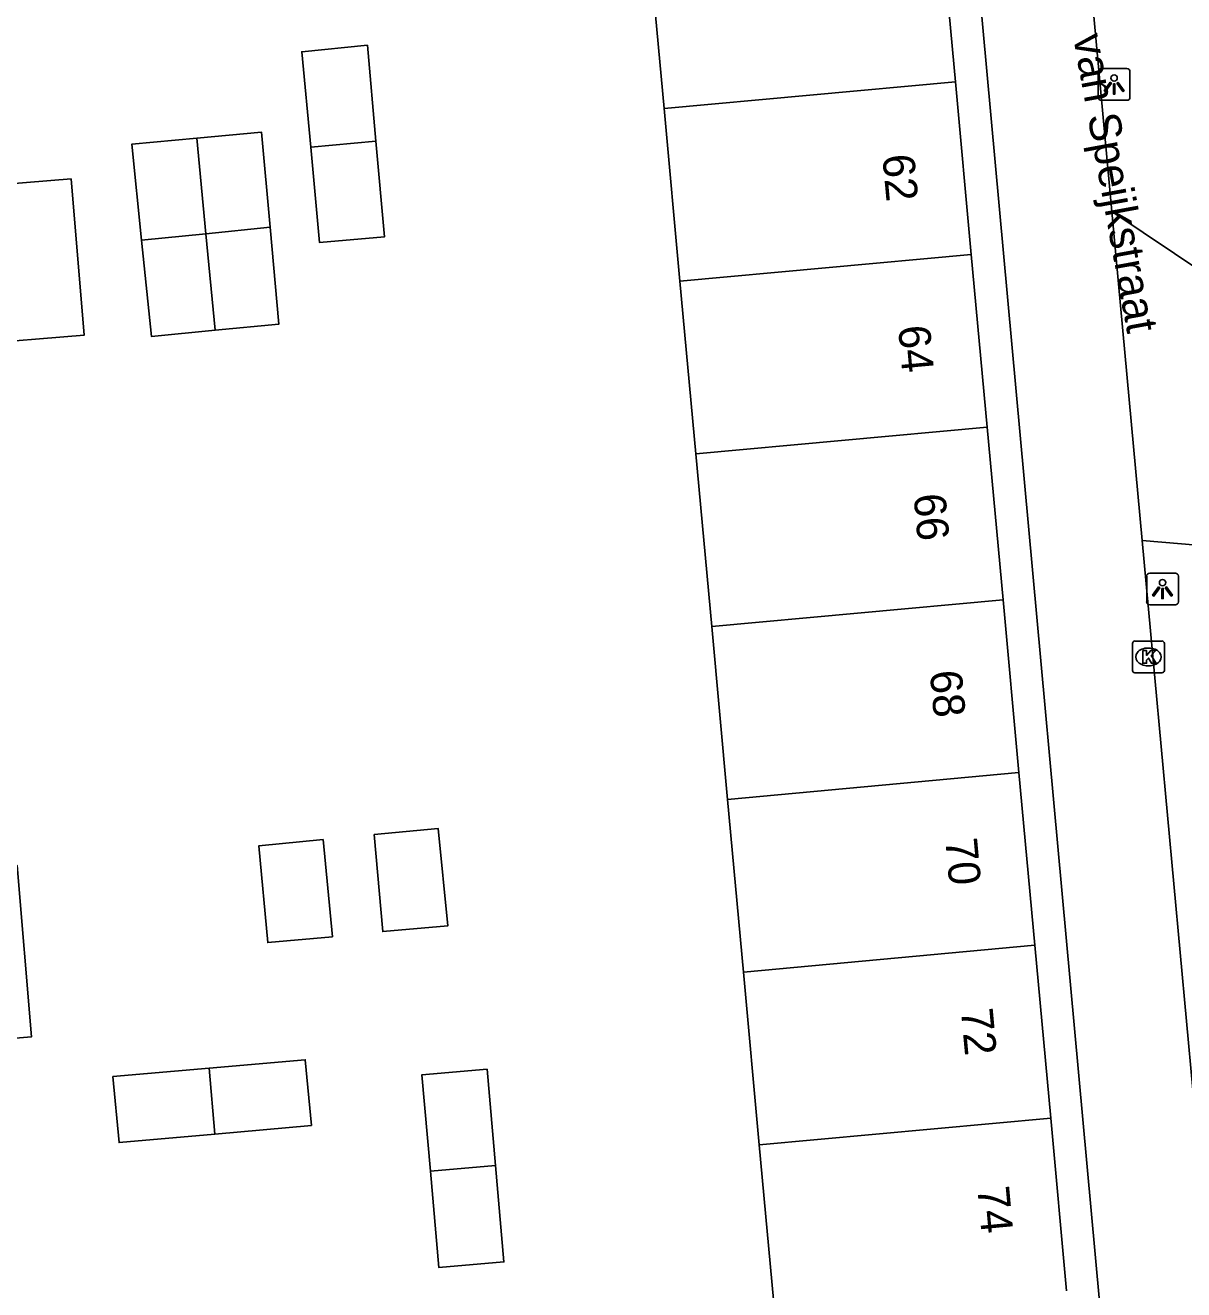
# Model space of a CAD drawing. Extents: x 160379 to 161131, y 383940 to 384849.
# Drawn here: x 160622.08 to 160658.49, y 384516.19 to 384555.93 of the extents above; entities that cross this region are included whole.
import ezdxf

# ---------------------------------------------------------------- set-up
doc = ezdxf.new("R2010")
doc.units = 0
for name, color, linetype in [('IMGEO_Groenvoorziening', 7, 'Continuous'), ('IMGEO_Kolk', 7, 'Continuous'), ('IMGEO_Lichtpunt', 7, 'Continuous'), ('IMGEO_Openbare_ruimte_label', 7, 'Continuous'), ('IMGEO_Pand', 7, 'Continuous'), ('IMGEO_Pand_nummerreeks', 7, 'Continuous'), ('IMGEO_Voetgangersgebied_open', 7, 'Continuous')]:
    doc.layers.add(name, color=color, linetype=linetype)

msp = doc.modelspace()

# ---------------------------------------------------------------- linework, layer by layer
at = {"layer": 'IMGEO_Groenvoorziening'}
msp.add_lwpolyline([(160656.229, 384550.075), (160661.151, 384546.774), (160661.917, 384545.486), (160662.071, 384542.104), (160661.684, 384540.236), (160660.94, 384539.438), (160659.532, 384539.533), (160657.181, 384539.738)], dxfattribs=at)
at = {"layer": 'IMGEO_Kolk'}
for p, q in [((160656.879, 384535.651), (160656.879, 384536.503)), ((160656.954, 384536.577), (160657.806, 384536.577)), ((160657.367, 384536.357), (160657.392, 384536.357)), ((160657.88, 384536.503), (160657.88, 384535.651)), ((160657.806, 384535.577), (160656.954, 384535.577)), ((160657.39, 384535.797), (160657.365, 384535.797))]:
    msp.add_line(p, q, dxfattribs=at)
for points in [[(160656.879, 384535.651), (160656.879, 384536.503)], [(160656.954, 384536.577), (160657.806, 384536.577)], [(160657.2, 384536.277), (160657.323, 384536.277), (160657.323, 384536.126), (160657.453, 384536.277), (160657.617, 384536.277), (160657.471, 384536.126), (160657.624, 384535.877), (160657.472, 384535.877), (160657.387, 384536.041), (160657.323, 384535.974), (160657.323, 384535.877), (160657.2, 384535.877), (160657.2, 384536.277)], [(160657.88, 384536.503), (160657.88, 384535.651)], [(160657.806, 384535.577), (160656.954, 384535.577)]]:
    msp.add_lwpolyline(points, dxfattribs=at)
for centre, start, end in [((160656.956, 384536.501), 91.552, 178.448), ((160656.956, 384536.501), 91.552, 178.448), ((160657.804, 384536.501), 1.552, 88.448), ((160657.804, 384536.501), 1.552, 88.448), ((160656.956, 384535.653), 181.552, 268.448), ((160656.956, 384535.653), 181.552, 268.448), ((160657.804, 384535.653), 271.552, 358.448), ((160657.804, 384535.653), 271.552, 358.448)]:
    msp.add_arc(centre, 0.0765, start, end, dxfattribs=at)
for centre, major_axis, ratio, start_param, end_param in [((160657.366, 384536.077), (-0.387, 0.002), 0.722429, 4.712389, 7.853982), ((160657.391, 384536.077), (-0.39, 0.002), 0.717154, 1.570796, 4.712389)]:
    msp.add_ellipse(centre, major_axis=major_axis, ratio=ratio, start_param=start_param, end_param=end_param, dxfattribs=at)
at = {"layer": 'IMGEO_Lichtpunt'}
for p, q in [((160656.706, 384554.568), (160655.898, 384554.568)), ((160656.706, 384554.568), (160655.898, 384554.568)), ((160655.804, 384554.473), (160655.804, 384553.666)), ((160655.804, 384554.473), (160655.804, 384553.666)), ((160656.8, 384553.666), (160656.8, 384554.473)), ((160656.8, 384553.666), (160656.8, 384554.473)), ((160655.898, 384553.572), (160656.706, 384553.572)), ((160655.898, 384553.572), (160656.706, 384553.572)), ((160658.227, 384538.71), (160657.419, 384538.71)), ((160658.227, 384538.71), (160657.419, 384538.71)), ((160657.325, 384538.615), (160657.325, 384537.808)), ((160657.325, 384538.615), (160657.325, 384537.808)), ((160658.321, 384537.808), (160658.321, 384538.615)), ((160658.321, 384537.808), (160658.321, 384538.615)), ((160657.419, 384537.714), (160658.227, 384537.714)), ((160657.419, 384537.714), (160658.227, 384537.714))]:
    msp.add_line(p, q, dxfattribs=at)
for points in [[(160656.178, 384554.137), (160656.217, 384554.109), (160656.029, 384553.847), (160655.991, 384553.874), (160656.178, 384554.137)], [(160656.28, 384554.089), (160656.327, 384554.089), (160656.327, 384553.767), (160656.28, 384553.767), (160656.28, 384554.089)], [(160656.39, 384554.109), (160656.428, 384554.136), (160656.615, 384553.874), (160656.576, 384553.846), (160656.39, 384554.109)], [(160657.699, 384538.279), (160657.738, 384538.251), (160657.55, 384537.989), (160657.512, 384538.016), (160657.699, 384538.279)], [(160657.911, 384538.251), (160657.949, 384538.278), (160658.136, 384538.016), (160658.097, 384537.988), (160657.911, 384538.251)], [(160657.801, 384538.231), (160657.848, 384538.231), (160657.848, 384537.909), (160657.801, 384537.909), (160657.801, 384538.231)]]:
    msp.add_lwpolyline(points, dxfattribs=at)
for centre in [(160656.303, 384554.271), (160657.824, 384538.413)]:
    msp.add_circle(centre, 0.0994, dxfattribs=at)
for centre, start, end in [((160655.898, 384554.473), 90, 180), ((160655.898, 384554.473), 90, 180), ((160656.706, 384554.473), 0, 90), ((160656.706, 384554.473), 0, 90), ((160655.898, 384553.666), 180, 270), ((160655.898, 384553.666), 180, 270), ((160656.706, 384553.666), 270, 0), ((160656.706, 384553.666), 270, 360), ((160657.419, 384538.615), 90, 180), ((160657.419, 384538.615), 90, 180), ((160658.227, 384538.615), 0, 90), ((160658.227, 384538.615), 0, 90), ((160657.419, 384537.808), 180, 270), ((160657.419, 384537.808), 180, 270), ((160658.227, 384537.808), 270, 0), ((160658.227, 384537.808), 270, 360)]:
    msp.add_arc(centre, 0.0946, start, end, dxfattribs=at)
at = {"layer": 'IMGEO_Pand'}
for points in [[(160642.161, 384553.314), (160641.662, 384558.742), (160650.813, 384559.589)], [(160650.813, 384559.589), (160651.313, 384554.154)], [(160631.054, 384552.1), (160630.774, 384555.098), (160632.834, 384555.303), (160633.101, 384552.29)], [(160642.161, 384553.314), (160651.313, 384554.154)], [(160651.313, 384554.154), (160651.813, 384548.726)], [(160642.659, 384547.885), (160642.161, 384553.314)], [(160627.479, 384552.382), (160629.508, 384552.567), (160629.776, 384549.584)], [(160625.741, 384549.174), (160625.434, 384552.196), (160627.479, 384552.382)], [(160627.762, 384549.38), (160627.479, 384552.382)], [(160633.101, 384552.29), (160633.369, 384549.277), (160631.333, 384549.101), (160631.054, 384552.1)], [(160633.101, 384552.29), (160631.054, 384552.1)], [(160619.944, 384550.806), (160623.524, 384551.103), (160623.931, 384546.19), (160620.351, 384545.893), (160620.374, 384545.619), (160614.454, 384545.127)], [(160629.776, 384549.584), (160627.762, 384549.38)], [(160629.776, 384549.584), (160630.051, 384546.531), (160628.049, 384546.342)], [(160627.762, 384549.38), (160625.741, 384549.174)], [(160628.049, 384546.342), (160626.047, 384546.153), (160625.741, 384549.174)], [(160627.762, 384549.38), (160628.049, 384546.342)], [(160651.813, 384548.726), (160642.659, 384547.885)], [(160651.813, 384548.726), (160652.312, 384543.297)], [(160643.158, 384542.457), (160642.659, 384547.885)], [(160652.312, 384543.297), (160643.158, 384542.457)], [(160652.312, 384543.297), (160652.811, 384537.869)], [(160643.656, 384537.028), (160643.158, 384542.457)], [(160652.811, 384537.869), (160643.656, 384537.028)], [(160652.811, 384537.869), (160653.311, 384532.44)], [(160644.155, 384531.6), (160643.656, 384537.028)], [(160653.311, 384532.44), (160644.155, 384531.6)], [(160653.311, 384532.44), (160653.81, 384527.012)], [(160644.653, 384526.171), (160644.155, 384531.6)], [(160631.449, 384530.337), (160631.734, 384527.284), (160629.705, 384527.098), (160629.424, 384530.144), (160631.449, 384530.337)], [(160633.047, 384530.494), (160635.062, 384530.683), (160635.36, 384527.623), (160633.316, 384527.446), (160633.047, 384530.494)], [(160615.911, 384529.024), (160621.83, 384529.519), (160622.28, 384524.138), (160613.146, 384523.374)], [(160653.81, 384527.012), (160644.653, 384526.171)], [(160653.81, 384527.012), (160654.31, 384521.584)], [(160645.152, 384520.743), (160644.653, 384526.171)], [(160627.862, 384523.15), (160630.885, 384523.415), (160631.074, 384521.352), (160628.044, 384521.081)], [(160628.044, 384521.081), (160625.031, 384520.812), (160624.839, 384522.884), (160627.862, 384523.15)], [(160627.862, 384523.15), (160628.044, 384521.081)], [(160634.814, 384519.911), (160634.544, 384522.937), (160636.596, 384523.115), (160636.86, 384520.093)], [(160645.152, 384520.743), (160654.31, 384521.584)], [(160654.31, 384521.584), (160654.809, 384516.155)], [(160645.65, 384515.314), (160645.152, 384520.743)], [(160636.86, 384520.093), (160637.126, 384517.059), (160635.083, 384516.885), (160634.814, 384519.911)], [(160636.86, 384520.093), (160634.814, 384519.911)]]:
    msp.add_lwpolyline(points, dxfattribs=at)
at = {"layer": 'IMGEO_Voetgangersgebied_open'}
for points in [[(160656.893, 384504.376), (160651.516, 384563.083), (160634.758, 384585.358)], [(160656.229, 384550.075), (160654.909, 384564.413), (160654.184, 384565.394)], [(160657.181, 384539.738), (160656.229, 384550.075)], [(160659.169, 384518.154), (160657.181, 384539.738)]]:
    msp.add_lwpolyline(points, dxfattribs=at)

# ---------------------------------------------------------------- texts
at = {"layer": 'IMGEO_Openbare_ruimte_label'}
msp.add_text('van Speijkstraat', height=1, rotation=280.3663, dxfattribs=at).set_placement((160655.009, 384555.571))
at = {"layer": 'IMGEO_Pand_nummerreeks'}
for s, p in [('62', (160649.016, 384551.839)), ('64', (160649.511, 384546.461)), ('66', (160649.997, 384541.172)), ('68', (160650.508, 384535.619)), ('70', (160650.993, 384530.345)), ('72', (160651.485, 384524.996)), ('74', (160652, 384519.403))]:
    msp.add_text(s, height=1, rotation=275.2595, dxfattribs=at).set_placement(p)

doc.saveas('drawing.dxf')
